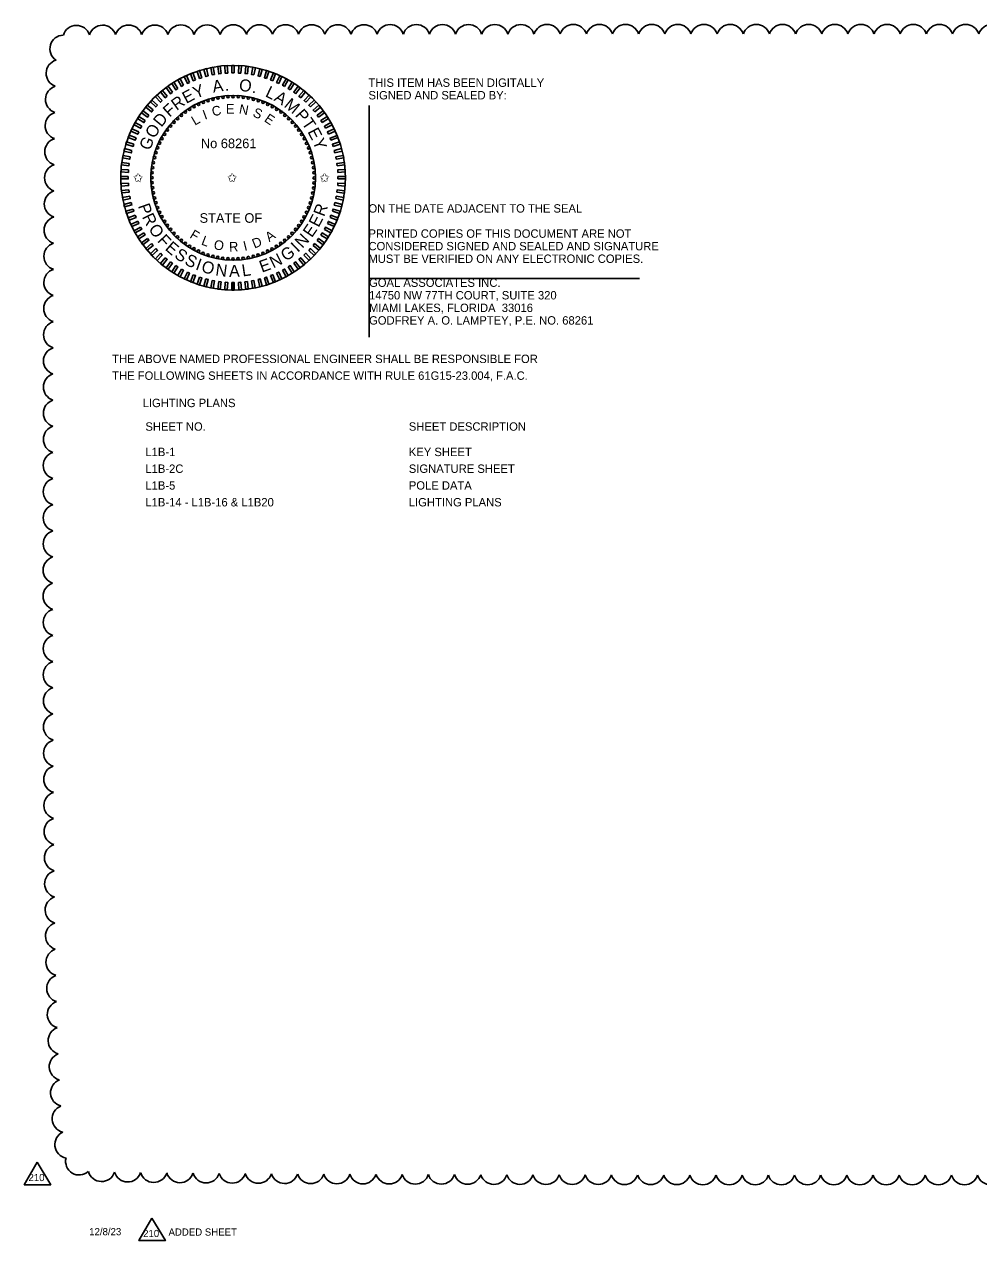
# Model space of a CAD drawing. Extents: x -811.2 to -795, y -2307.6 to -2235.1.
# Drawn here: x -811.23 to -803.27, y -2282.51 to -2272.36 of the extents above; entities that cross this region are included whole.
import ezdxf

# ---------------------------------------------------------------- set-up
doc = ezdxf.new("R2010")
doc.units = 0
for name, color, linetype in [('AdhocPoint_dp', 7, 'Continuous'), ('Cloud_dp', 7, 'Continuous'), ('Logo_dp', 7, 'Continuous'), ('TeleMisc', 7, 'Continuous'), ('TextDetails', 7, 'Continuous'), ('TextMinor', 7, 'Continuous'), ('TextMisc', 7, 'Continuous')]:
    doc.layers.add(name, color=color, linetype=linetype)

msp = doc.modelspace()

# ---------------------------------------------------------------- linework, layer by layer
at = {"layer": 'AdhocPoint_dp'}
for p, q in [((-808.355, -2273.035), (-808.355, -2274.969)), ((-808.355, -2274.479), (-806.098, -2274.479))]:
    msp.add_line(p, q, dxfattribs=at)
at = {"layer": 'Cloud_dp'}
for points in [[(-811.125, -2281.857), (-811.233, -2282.045), (-811.012, -2282.045)], [(-810.168, -2282.324), (-810.276, -2282.512), (-810.055, -2282.512)]]:
    msp.add_lwpolyline(points, close=True, dxfattribs=at)
for centre, start, end in [((-810.798, -2272.48), 18.0566, 163.0566), ((-810.58, -2272.478), 17.7998, 162.7998), ((-810.362, -2272.477), 17.7187, 162.7187), ((-810.143, -2272.477), 17.6743, 162.6743), ((-809.925, -2272.476), 17.6451, 162.6451), ((-809.707, -2272.476), 17.624, 162.624), ((-809.488, -2272.475), 17.6079, 162.6079), ((-809.27, -2272.475), 17.5951, 162.5951), ((-809.052, -2272.474), 17.5845, 162.5845), ((-808.834, -2272.474), 17.5756, 162.5756), ((-808.615, -2272.474), 17.568, 162.568), ((-808.397, -2272.474), 17.5614, 162.5614), ((-808.179, -2272.473), 17.5556, 162.5556), ((-807.96, -2272.473), 17.5505, 162.5505), ((-807.742, -2272.473), 17.5459, 162.5459), ((-807.524, -2272.473), 17.5417, 162.5417), ((-807.305, -2272.473), 17.5379, 162.5379), ((-807.087, -2272.473), 17.5344, 162.5344), ((-806.869, -2272.472), 17.5313, 162.5313), ((-806.65, -2272.472), 17.5283, 162.5283), ((-806.432, -2272.472), 17.5256, 162.5256), ((-806.214, -2272.472), 17.5231, 162.5231), ((-805.995, -2272.472), 17.5207, 162.5207), ((-805.777, -2272.472), 17.5185, 162.5185), ((-805.559, -2272.472), 17.5164, 162.5164), ((-805.34, -2272.472), 17.5145, 162.5145), ((-805.122, -2272.472), 17.5126, 162.5126), ((-804.904, -2272.472), 17.5109, 162.5109), ((-804.685, -2272.472), 17.5092, 162.5092), ((-804.467, -2272.472), 17.5077, 162.5077), ((-804.249, -2272.472), 17.5062, 162.5062), ((-804.03, -2272.472), 17.5048, 162.5048), ((-803.812, -2272.472), 17.5034, 162.5034), ((-803.594, -2272.472), 17.5021, 162.5021), ((-803.375, -2272.472), 17.5009, 162.5009), ((-803.157, -2272.472), 17.5, 162.5), ((-810.905, -2272.561), 91.4771, 236.4771), ((-810.937, -2272.766), 105.908, 250.908), ((-810.942, -2272.984), 106.4168, 251.4168), ((-810.945, -2273.203), 106.6762, 251.6762), ((-810.948, -2273.421), 106.841, 251.841), ((-810.95, -2273.639), 106.9576, 251.9576), ((-810.952, -2273.857), 107.0457, 252.0457), ((-810.954, -2274.076), 107.1154, 252.1154), ((-810.955, -2274.294), 107.1722, 252.1722), ((-810.956, -2274.512), 107.2198, 252.2198), ((-810.957, -2274.73), 107.2603, 252.2603), ((-810.958, -2274.949), 107.2954, 252.2954), ((-810.959, -2275.167), 107.3262, 252.3262), ((-810.96, -2275.385), 107.3535, 252.3535), ((-810.96, -2275.604), 107.3779, 252.3779), ((-810.96, -2275.822), 107.3998, 252.3998), ((-810.961, -2276.04), 107.4198, 252.4198), ((-810.961, -2276.259), 107.438, 252.438), ((-810.961, -2276.477), 107.4547, 252.4547), ((-810.961, -2276.695), 107.4701, 252.4701), ((-810.962, -2276.914), 107.4843, 252.4843), ((-810.962, -2277.132), 107.499, 252.499), ((-810.961, -2277.35), 107.5356, 252.5356), ((-810.961, -2277.568), 107.5822, 252.5822), ((-810.961, -2277.787), 107.6325, 252.6325), ((-810.96, -2278.005), 107.6869, 252.6869), ((-810.959, -2278.223), 107.7461, 252.7461), ((-810.958, -2278.442), 107.8108, 252.8108), ((-810.957, -2278.66), 107.8818, 252.8818), ((-810.955, -2278.878), 107.9604, 252.9604), ((-810.954, -2279.096), 108.0479, 253.0479), ((-810.951, -2279.315), 108.1461, 253.1461), ((-810.949, -2279.533), 108.2576, 253.2576), ((-810.945, -2279.751), 108.3854, 253.3854), ((-810.942, -2279.969), 108.534, 253.534), ((-810.938, -2280.187), 108.7099, 253.7099), ((-810.932, -2280.406), 108.9225, 253.9225), ((-810.927, -2280.624), 109.1867, 254.1867), ((-810.92, -2280.842), 109.5275, 254.5275), ((-810.911, -2281.06), 109.9909, 254.9909), ((-810.9, -2281.277), 110.6749, 255.6749), ((-810.886, -2281.494), 111.8417, 256.8417), ((-810.864, -2281.71), 114.6718, 259.6718), ((-810.774, -2281.85), 166.2299, 311.2299), ((-810.588, -2281.904), 196.1072, 341.1072), ((-810.37, -2281.908), 196.5738, 341.5738), ((-810.152, -2281.912), 196.7877, 341.7877), ((-809.934, -2281.914), 196.9179, 341.9179), ((-809.715, -2281.916), 197.008, 342.008), ((-809.497, -2281.918), 197.075, 342.075), ((-809.279, -2281.919), 197.1274, 342.1274), ((-809.061, -2281.921), 197.1699, 342.1699), ((-808.842, -2281.922), 197.2052, 342.2052), ((-808.624, -2281.923), 197.2352, 342.2352), ((-808.406, -2281.924), 197.261, 342.261), ((-808.187, -2281.925), 197.2836, 342.2836), ((-807.969, -2281.926), 197.3036, 342.3036), ((-807.751, -2281.926), 197.3214, 342.3214), ((-807.532, -2281.927), 197.3374, 342.3374), ((-807.314, -2281.928), 197.3519, 342.3519), ((-807.096, -2281.928), 197.3651, 342.3651), ((-806.878, -2281.929), 197.3773, 342.3773), ((-806.659, -2281.929), 197.3884, 342.3884), ((-806.441, -2281.929), 197.3987, 342.3987), ((-806.223, -2281.93), 197.4083, 342.4083), ((-806.004, -2281.93), 197.4172, 342.4172), ((-805.786, -2281.93), 197.4256, 342.4256), ((-805.568, -2281.931), 197.4334, 342.4334), ((-805.349, -2281.931), 197.4407, 342.4407), ((-805.131, -2281.931), 197.4476, 342.4476), ((-804.913, -2281.931), 197.4542, 342.4542), ((-804.694, -2281.931), 197.4604, 342.4604), ((-804.476, -2281.932), 197.4662, 342.4662), ((-804.258, -2281.932), 197.4718, 342.4718), ((-804.039, -2281.932), 197.4771, 342.4771), ((-803.821, -2281.932), 197.4821, 342.4821), ((-803.603, -2281.932), 197.487, 342.487), ((-803.384, -2281.932), 197.4916, 342.4916), ((-803.166, -2281.932), 197.496, 342.496)]:
    msp.add_arc(centre, 0.114, start, end, dxfattribs=at)
at = {"layer": 'TextDetails'}
for radius in [0.938, 0.688]:
    msp.add_circle((-809.49, -2273.638), radius, dxfattribs=at)
at = {"layer": 'TextMisc'}
for p, q in [((-809.5, -2274.576), (-809.5, -2274.513)), ((-809.49, -2274.576), (-809.49, -2274.513)), ((-809.48, -2274.576), (-809.48, -2274.513))]:
    msp.add_line(p, q, dxfattribs=at)
for points in [[(-809.59, -2272.769), (-809.61, -2272.771), (-809.618, -2272.709), (-809.598, -2272.707)], [(-809.535, -2272.764), (-809.555, -2272.765), (-809.559, -2272.703), (-809.539, -2272.702)], [(-809.48, -2272.763), (-809.5, -2272.763), (-809.5, -2272.701), (-809.48, -2272.701)], [(-809.425, -2272.765), (-809.445, -2272.764), (-809.441, -2272.702), (-809.421, -2272.703)], [(-809.37, -2272.771), (-809.39, -2272.769), (-809.383, -2272.707), (-809.363, -2272.709)], [(-809.903, -2272.866), (-809.92, -2272.876), (-809.951, -2272.821), (-809.933, -2272.812)], [(-809.853, -2272.842), (-809.872, -2272.851), (-809.898, -2272.794), (-809.88, -2272.785)], [(-809.803, -2272.821), (-809.822, -2272.828), (-809.845, -2272.77), (-809.826, -2272.763)], [(-809.751, -2272.803), (-809.77, -2272.809), (-809.789, -2272.75), (-809.77, -2272.743)], [(-809.698, -2272.788), (-809.717, -2272.793), (-809.733, -2272.733), (-809.713, -2272.727)], [(-809.644, -2272.777), (-809.664, -2272.78), (-809.676, -2272.719), (-809.656, -2272.715)], [(-809.316, -2272.78), (-809.336, -2272.777), (-809.324, -2272.715), (-809.304, -2272.719)], [(-809.263, -2272.793), (-809.282, -2272.788), (-809.267, -2272.728), (-809.247, -2272.733)], [(-809.21, -2272.809), (-809.229, -2272.803), (-809.21, -2272.743), (-809.191, -2272.75)], [(-809.159, -2272.828), (-809.177, -2272.821), (-809.154, -2272.763), (-809.136, -2272.77)], [(-809.108, -2272.851), (-809.127, -2272.842), (-809.1, -2272.786), (-809.082, -2272.794)], [(-809.06, -2272.876), (-809.077, -2272.866), (-809.047, -2272.812), (-809.03, -2272.821)], [(-810.04, -2272.957), (-810.056, -2272.97), (-810.095, -2272.922), (-810.08, -2272.909)], [(-809.996, -2272.924), (-810.013, -2272.936), (-810.049, -2272.885), (-810.033, -2272.874)], [(-809.95, -2272.894), (-809.967, -2272.905), (-810.001, -2272.852), (-809.984, -2272.841)], [(-809.013, -2272.905), (-809.03, -2272.894), (-808.996, -2272.841), (-808.979, -2272.852)], [(-808.968, -2272.936), (-808.984, -2272.924), (-808.947, -2272.874), (-808.931, -2272.886)], [(-808.925, -2272.97), (-808.94, -2272.957), (-808.9, -2272.909), (-808.885, -2272.922)], [(-810.121, -2273.032), (-810.135, -2273.046), (-810.18, -2273.004), (-810.167, -2272.989)], [(-810.082, -2272.993), (-810.096, -2273.007), (-810.139, -2272.962), (-810.124, -2272.948)], [(-808.884, -2273.007), (-808.898, -2272.993), (-808.856, -2272.948), (-808.841, -2272.962)], [(-808.845, -2273.046), (-808.859, -2273.032), (-808.814, -2272.989), (-808.8, -2273.004)], [(-810.192, -2273.115), (-810.204, -2273.132), (-810.254, -2273.095), (-810.243, -2273.079)], [(-810.158, -2273.072), (-810.171, -2273.088), (-810.219, -2273.048), (-810.206, -2273.033)], [(-808.809, -2273.088), (-808.822, -2273.073), (-808.774, -2273.033), (-808.761, -2273.048)], [(-808.776, -2273.132), (-808.788, -2273.116), (-808.738, -2273.079), (-808.726, -2273.095)], [(-810.252, -2273.208), (-810.262, -2273.225), (-810.316, -2273.195), (-810.307, -2273.177)], [(-810.223, -2273.161), (-810.234, -2273.178), (-810.287, -2273.144), (-810.276, -2273.127)], [(-808.746, -2273.178), (-808.757, -2273.161), (-808.704, -2273.127), (-808.693, -2273.144)], [(-808.718, -2273.225), (-808.728, -2273.208), (-808.673, -2273.178), (-808.664, -2273.195)], [(-810.3, -2273.306), (-810.307, -2273.325), (-810.365, -2273.302), (-810.358, -2273.283)], [(-810.278, -2273.256), (-810.286, -2273.275), (-810.343, -2273.248), (-810.334, -2273.23)], [(-808.694, -2273.275), (-808.703, -2273.256), (-808.646, -2273.23), (-808.638, -2273.248)], [(-808.673, -2273.325), (-808.68, -2273.307), (-808.622, -2273.284), (-808.615, -2273.302)], [(-810.335, -2273.411), (-810.34, -2273.43), (-810.401, -2273.415), (-810.396, -2273.395)], [(-810.319, -2273.358), (-810.325, -2273.377), (-810.385, -2273.358), (-810.379, -2273.339)], [(-808.655, -2273.377), (-808.661, -2273.358), (-808.602, -2273.339), (-808.595, -2273.358)], [(-808.64, -2273.43), (-808.645, -2273.411), (-808.585, -2273.395), (-808.58, -2273.415)], [(-810.357, -2273.518), (-810.36, -2273.538), (-810.421, -2273.53), (-810.419, -2273.51)], [(-810.348, -2273.464), (-810.352, -2273.484), (-810.413, -2273.472), (-810.409, -2273.452)], [(-808.629, -2273.484), (-808.632, -2273.464), (-808.571, -2273.453), (-808.567, -2273.472)], [(-808.621, -2273.538), (-808.623, -2273.518), (-808.561, -2273.511), (-808.559, -2273.531)], [(-810.363, -2273.573), (-810.364, -2273.593), (-810.426, -2273.589), (-810.425, -2273.569)], [(-808.616, -2273.593), (-808.617, -2273.573), (-808.555, -2273.569), (-808.554, -2273.589)], [(-810.365, -2273.628), (-810.365, -2273.648), (-810.428, -2273.648), (-810.428, -2273.628)], [(-810.364, -2273.683), (-810.363, -2273.703), (-810.425, -2273.707), (-810.426, -2273.687)], [(-808.617, -2273.703), (-808.616, -2273.683), (-808.554, -2273.687), (-808.555, -2273.707)], [(-808.615, -2273.648), (-808.615, -2273.628), (-808.553, -2273.628), (-808.553, -2273.648)], [(-810.36, -2273.738), (-810.357, -2273.758), (-810.419, -2273.765), (-810.421, -2273.745)], [(-810.352, -2273.792), (-810.348, -2273.812), (-810.409, -2273.824), (-810.413, -2273.804)], [(-808.632, -2273.812), (-808.629, -2273.792), (-808.567, -2273.804), (-808.571, -2273.824)], [(-808.623, -2273.758), (-808.621, -2273.738), (-808.559, -2273.746), (-808.561, -2273.766)], [(-810.34, -2273.846), (-810.335, -2273.865), (-810.396, -2273.881), (-810.401, -2273.861)], [(-810.325, -2273.899), (-810.319, -2273.918), (-810.379, -2273.937), (-810.385, -2273.918)], [(-808.661, -2273.918), (-808.655, -2273.899), (-808.595, -2273.918), (-808.602, -2273.937)], [(-808.645, -2273.866), (-808.64, -2273.846), (-808.58, -2273.861), (-808.585, -2273.881)], [(-810.307, -2273.951), (-810.3, -2273.969), (-810.358, -2273.992), (-810.366, -2273.974)], [(-810.286, -2274.001), (-810.278, -2274.02), (-810.334, -2274.046), (-810.343, -2274.028)], [(-808.703, -2274.02), (-808.694, -2274.002), (-808.638, -2274.028), (-808.646, -2274.046)], [(-808.68, -2273.97), (-808.673, -2273.951), (-808.615, -2273.974), (-808.622, -2273.993)], [(-810.262, -2274.051), (-810.252, -2274.068), (-810.307, -2274.098), (-810.317, -2274.081)], [(-810.234, -2274.098), (-810.224, -2274.115), (-810.276, -2274.149), (-810.287, -2274.132)], [(-808.757, -2274.116), (-808.746, -2274.098), (-808.693, -2274.132), (-808.704, -2274.149)], [(-808.728, -2274.069), (-808.719, -2274.051), (-808.664, -2274.081), (-808.674, -2274.099)], [(-810.204, -2274.144), (-810.192, -2274.16), (-810.243, -2274.197), (-810.255, -2274.181)], [(-810.171, -2274.188), (-810.158, -2274.204), (-810.206, -2274.243), (-810.219, -2274.228)], [(-810.135, -2274.23), (-810.121, -2274.244), (-810.167, -2274.287), (-810.18, -2274.272)], [(-808.859, -2274.244), (-808.845, -2274.23), (-808.8, -2274.272), (-808.814, -2274.287)], [(-808.822, -2274.204), (-808.81, -2274.188), (-808.761, -2274.228), (-808.774, -2274.243)], [(-808.788, -2274.161), (-808.776, -2274.144), (-808.726, -2274.181), (-808.738, -2274.197)], [(-810.097, -2274.269), (-810.082, -2274.283), (-810.125, -2274.328), (-810.139, -2274.314)], [(-810.056, -2274.306), (-810.04, -2274.319), (-810.08, -2274.367), (-810.096, -2274.354)], [(-808.94, -2274.319), (-808.925, -2274.306), (-808.885, -2274.354), (-808.9, -2274.367)], [(-808.899, -2274.283), (-808.884, -2274.269), (-808.841, -2274.315), (-808.856, -2274.328)], [(-810.013, -2274.34), (-809.996, -2274.352), (-810.033, -2274.402), (-810.049, -2274.39)], [(-809.968, -2274.371), (-809.951, -2274.382), (-809.984, -2274.435), (-810.001, -2274.424)], [(-809.921, -2274.4), (-809.903, -2274.41), (-809.933, -2274.464), (-809.951, -2274.455)], [(-809.872, -2274.425), (-809.854, -2274.434), (-809.88, -2274.491), (-809.898, -2274.482)], [(-809.127, -2274.434), (-809.109, -2274.426), (-809.082, -2274.482), (-809.1, -2274.491)], [(-809.077, -2274.41), (-809.06, -2274.4), (-809.03, -2274.455), (-809.047, -2274.464)], [(-809.03, -2274.382), (-809.013, -2274.371), (-808.979, -2274.424), (-808.996, -2274.435)], [(-808.984, -2274.352), (-808.968, -2274.34), (-808.931, -2274.391), (-808.947, -2274.402)], [(-809.822, -2274.448), (-809.803, -2274.455), (-809.826, -2274.513), (-809.845, -2274.506)], [(-809.77, -2274.467), (-809.751, -2274.473), (-809.77, -2274.533), (-809.79, -2274.526)], [(-809.718, -2274.483), (-809.698, -2274.488), (-809.714, -2274.549), (-809.733, -2274.544)], [(-809.664, -2274.496), (-809.644, -2274.499), (-809.656, -2274.561), (-809.676, -2274.557)], [(-809.61, -2274.505), (-809.59, -2274.507), (-809.598, -2274.569), (-809.618, -2274.567)], [(-809.555, -2274.511), (-809.535, -2274.512), (-809.539, -2274.574), (-809.559, -2274.573)], [(-809.5, -2274.513), (-809.48, -2274.513), (-809.48, -2274.576), (-809.5, -2274.576)], [(-809.445, -2274.512), (-809.425, -2274.511), (-809.421, -2274.573), (-809.441, -2274.574)], [(-809.391, -2274.507), (-809.371, -2274.505), (-809.363, -2274.567), (-809.383, -2274.569)], [(-809.336, -2274.499), (-809.316, -2274.496), (-809.305, -2274.557), (-809.324, -2274.561)], [(-809.282, -2274.488), (-809.263, -2274.483), (-809.247, -2274.544), (-809.267, -2274.549)], [(-809.229, -2274.473), (-809.21, -2274.467), (-809.191, -2274.527), (-809.21, -2274.533)], [(-809.177, -2274.455), (-809.159, -2274.448), (-809.136, -2274.506), (-809.154, -2274.513)]]:
    msp.add_lwpolyline(points, close=True, dxfattribs=at)
for centre in [(-809.778, -2273.025), (-809.739, -2273.008), (-809.699, -2272.994), (-809.658, -2272.982), (-809.617, -2272.972), (-809.574, -2272.966), (-809.532, -2272.962), (-809.49, -2272.961), (-809.447, -2272.962), (-809.405, -2272.966), (-809.363, -2272.973), (-809.321, -2272.982), (-809.28, -2272.994), (-809.24, -2273.008), (-809.201, -2273.025), (-809.922, -2273.116), (-809.888, -2273.09), (-809.853, -2273.066), (-809.816, -2273.044), (-809.163, -2273.045), (-809.127, -2273.066), (-809.091, -2273.09), (-809.058, -2273.116), (-810.012, -2273.206), (-809.984, -2273.174), (-809.953, -2273.144), (-809.026, -2273.145), (-808.996, -2273.175), (-808.968, -2273.207), (-810.084, -2273.311), (-810.062, -2273.275), (-810.038, -2273.239), (-808.942, -2273.24), (-808.918, -2273.276), (-808.896, -2273.312), (-810.134, -2273.428), (-810.12, -2273.388), (-810.103, -2273.349), (-808.877, -2273.35), (-808.86, -2273.389), (-808.846, -2273.429), (-810.155, -2273.511), (-810.146, -2273.469), (-808.834, -2273.47), (-808.825, -2273.512), (-810.166, -2273.595), (-810.162, -2273.553), (-808.818, -2273.554), (-808.814, -2273.596), (-810.168, -2273.637), (-810.166, -2273.68), (-810.162, -2273.722), (-808.818, -2273.724), (-808.814, -2273.681), (-808.813, -2273.639), (-810.156, -2273.764), (-810.146, -2273.806), (-808.834, -2273.807), (-808.825, -2273.766), (-810.135, -2273.847), (-810.12, -2273.887), (-810.103, -2273.926), (-808.877, -2273.927), (-808.86, -2273.888), (-808.846, -2273.848), (-810.084, -2273.964), (-810.062, -2274.001), (-810.039, -2274.036), (-808.942, -2274.037), (-808.918, -2274.002), (-808.897, -2273.965), (-810.012, -2274.069), (-809.984, -2274.101), (-809.954, -2274.132), (-809.027, -2274.132), (-808.997, -2274.102), (-808.968, -2274.07), (-809.922, -2274.16), (-809.889, -2274.186), (-809.854, -2274.21), (-809.817, -2274.231), (-809.164, -2274.232), (-809.128, -2274.21), (-809.092, -2274.186), (-809.059, -2274.16), (-809.779, -2274.251), (-809.74, -2274.268), (-809.7, -2274.282), (-809.659, -2274.294), (-809.618, -2274.303), (-809.576, -2274.31), (-809.533, -2274.314), (-809.49, -2274.316), (-809.448, -2274.314), (-809.406, -2274.31), (-809.364, -2274.304), (-809.322, -2274.294), (-809.281, -2274.283), (-809.241, -2274.268), (-809.202, -2274.251)]:
    msp.add_circle(centre, 0.01, dxfattribs=at)

# ---------------------------------------------------------------- texts
at = {"layer": 'Cloud_dp'}
for p in [(-811.198, -2282.015), (-810.241, -2282.482)]:
    msp.add_text('210', height=0.06, rotation=0, dxfattribs=at).set_placement(p)
at = {"layer": 'Logo_dp'}
for s, p in [('THIS ITEM HAS BEEN DIGITALLY', (-808.36, -2272.879)), ('SIGNED AND SEALED BY:', (-808.36, -2272.984)), ('ON THE DATE ADJACENT TO THE SEAL', (-808.36, -2273.929)), ('PRINTED COPIES OF THIS DOCUMENT ARE NOT ', (-808.36, -2274.139)), ('CONSIDERED SIGNED AND SEALED AND SIGNATURE ', (-808.36, -2274.244)), ('MUST BE VERIFIED ON ANY ELECTRONIC COPIES.', (-808.36, -2274.349)), ('GOAL ASSOCIATES INC.', (-808.355, -2274.549)), ('14750 NW 77TH COURT, SUITE 320', (-808.355, -2274.654)), ('MIAMI LAKES, FLORIDA  33016', (-808.355, -2274.759)), ('GODFREY A. O. LAMPTEY, P.E. NO. 68261', (-808.355, -2274.864)), ('THE ABOVE NAMED PROFESSIONAL ENGINEER SHALL BE RESPONSIBLE FOR ', (-810.499, -2275.185)), ('THE FOLLOWING SHEETS IN ACCORDANCE WITH RULE 61G15-23.004, F.A.C.', (-810.499, -2275.325)), ('LIGHTING PLANS', (-810.245, -2275.553))]:
    msp.add_text(s, height=0.07, dxfattribs=at).set_placement(p)
at = {"layer": 'TeleMisc'}
for s, p in [('SHEET NO.', (-810.222, -2275.75)), ('SHEET DESCRIPTION', (-808.023, -2275.75)), ('L1B-1', (-810.222, -2275.962)), ('KEY SHEET', (-808.023, -2275.962)), ('L1B-2C', (-810.222, -2276.102)), ('SIGNATURE SHEET', (-808.023, -2276.102)), ('L1B-5', (-810.222, -2276.242)), ('POLE DATA', (-808.023, -2276.242)), ('L1B-14 - L1B-16 & L1B20', (-810.222, -2276.382)), ('LIGHTING PLANS', (-808.023, -2276.382))]:
    msp.add_text(s, height=0.07, dxfattribs=at).set_placement(p)
at = {"layer": 'TextMinor'}
for s, p in [('12/8/23', (-810.691, -2282.467)), ('ADDED SHEET', (-810.029, -2282.47))]:
    msp.add_text(s, height=0.06, dxfattribs=at).set_placement(p)
at = {"layer": 'TextMisc'}
for s, height, rotation, p in [('E', 0.1, 28.1055, (-809.881, -2273.022)), ('Y', 0.1, 21.0633, (-809.802, -2272.979)), ('A', 0.1, 8.8088, (-809.655, -2272.927)), ('.', 0.1, 1.0418, (-809.558, -2272.912)), ('O', 0.1, 352.1877, (-809.445, -2272.91)), ('.', 0.1, 343.5268, (-809.336, -2272.925)), ('L', 0.1, 334.6727, (-809.228, -2272.957)), ('F', 0.1, 42.3772, (-810.02, -2273.137)), ('R', 0.1, 35.9269, (-809.961, -2273.081)), ('A', 0.1, 328.4096, (-809.155, -2272.99)), ('M', 0.1, 320.6426, (-809.071, -2273.041)), ('D', 0.1, 50.8569, (-810.089, -2273.221)), ('I', 0.08, 20.0117, (-809.726, -2273.154)), ('C', 0.08, 12.2025, (-809.658, -2273.126)), ('E', 0.08, 0.4186, (-809.55, -2273.103)), ('N', 0.08, 349.2914, (-809.445, -2273.101)), ('S', 0.08, 337.0221, (-809.332, -2273.123)), ('E', 0.08, 325.8663, (-809.236, -2273.163)), ('P', 0.1, 311.1966, (-808.978, -2273.118)), ('O', 0.1, 59.5178, (-810.145, -2273.316)), ('L', 0.08, 30.4021, (-809.809, -2273.204)), ('T', 0.1, 304.4563, (-808.921, -2273.182)), ('E', 0.1, 297.6315, (-808.871, -2273.253)), ('G', 0.1, 68.0518, (-810.185, -2273.416)), ('Y', 0.1, 290.5893, (-808.828, -2273.331)), ('P', 0.1, 289.4055, (-810.285, -2273.873)), ('R', 0.1, 296.1458, (-810.252, -2273.964)), ('R', 0.1, 69.5134, (-808.73, -2273.968)), ('O', 0.1, 303.9671, (-810.2, -2274.065)), ('E', 0.1, 55.4289, (-808.833, -2274.143)), ('E', 0.1, 62.4712, (-808.776, -2274.058)), ('F', 0.1, 312.628, (-810.128, -2274.167)), ('F', 0.08, 328.7241, (-809.858, -2274.135)), ('L', 0.08, 339.2916, (-809.761, -2274.194)), ('A', 0.08, 34.4992, (-809.188, -2274.177)), ('N', 0.1, 47.1788, (-808.912, -2274.232)), ('E', 0.1, 319.0783, (-810.064, -2274.235)), ('S', 0.1, 326.1206, (-809.987, -2274.301)), ('O', 0.08, 349.6821, (-809.656, -2274.233)), ('R', 0.08, 2.3398, (-809.522, -2274.255)), ('I', 0.08, 14.2037, (-809.394, -2274.249)), ('D', 0.08, 22.0128, (-809.312, -2274.23)), ('G', 0.1, 35.1115, (-809.049, -2274.34)), ('I', 0.1, 43.6456, (-808.95, -2274.266)), ('S', 0.1, 333.193, (-809.902, -2274.357)), ('I', 0.1, 340.2654, (-809.81, -2274.402)), ('O', 0.1, 343.7986, (-809.762, -2274.421)), ('E', 0.1, 19.8191, (-809.25, -2274.431)), ('N', 0.1, 26.8614, (-809.154, -2274.396)), ('N', 0.1, 352.4595, (-809.641, -2274.453)), ('A', 0.1, 0.7097, (-809.523, -2274.466)), ('L', 0.1, 8.4767, (-809.41, -2274.463))]:
    msp.add_text(s, height=height, rotation=rotation, dxfattribs=at).set_placement(p)
for s, p in [('No 68261', (-809.759, -2273.391)), ('✩', (-810.325, -2273.676)), ('✩', (-809.54, -2273.676)), ('✩', (-808.769, -2273.676)), ('STATE OF', (-809.77, -2274.014))]:
    msp.add_text(s, height=0.08, dxfattribs=at).set_placement(p)

doc.saveas('drawing.dxf')
